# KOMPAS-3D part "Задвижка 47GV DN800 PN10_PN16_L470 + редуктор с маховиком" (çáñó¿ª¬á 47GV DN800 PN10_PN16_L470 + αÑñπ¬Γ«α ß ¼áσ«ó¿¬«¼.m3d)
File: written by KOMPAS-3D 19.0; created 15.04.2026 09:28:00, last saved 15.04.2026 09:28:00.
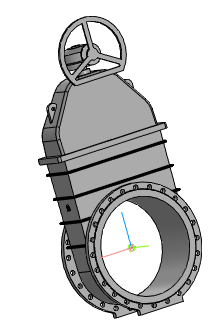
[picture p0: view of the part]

Document properties: Автор: Энергия; Полное имя файла: ..\..\Задвижка 47GV DN800 PN10_PN16_L470 + редуктор с маховиком.a3d

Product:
- Part/product: Задвижка 47GV DN800 PN10_PN16_L470 + редуктор с маховиком
    Масса: 2647.52

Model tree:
1. Операция без истории:1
